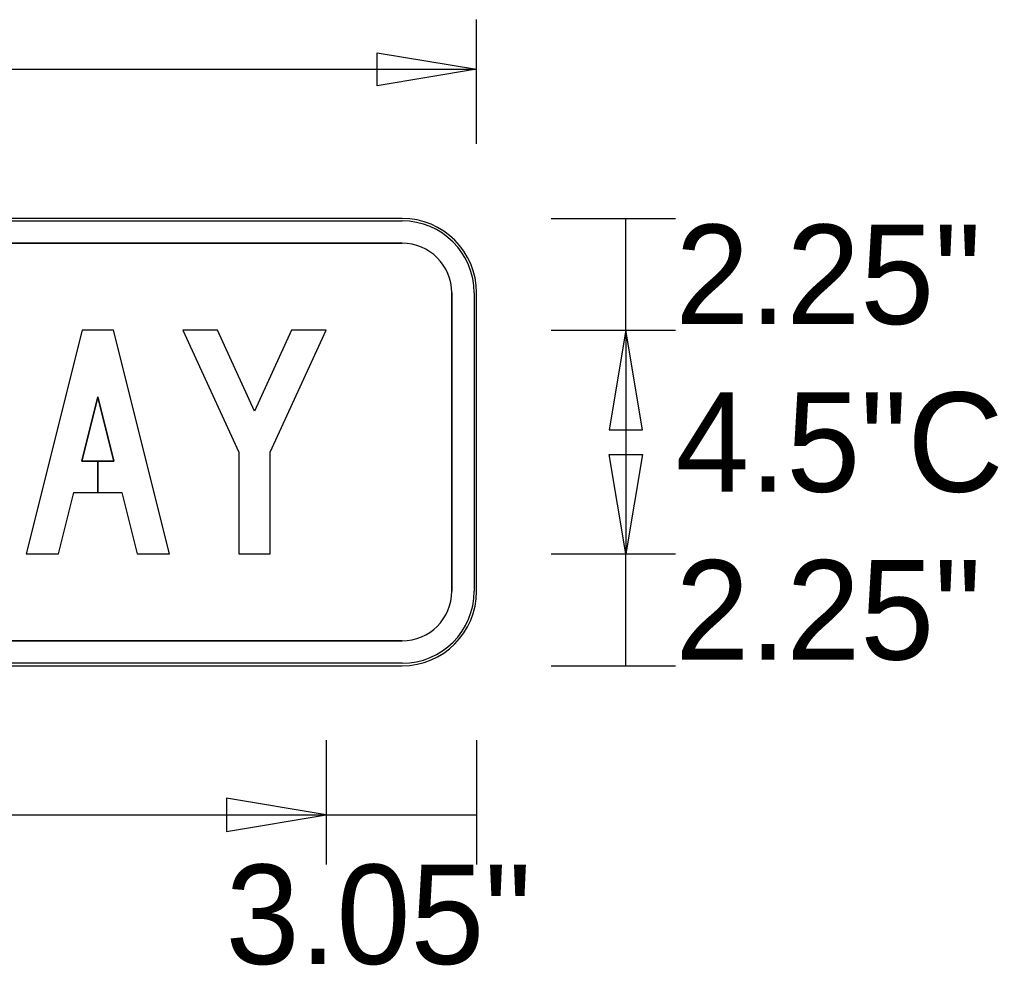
# Model space of a CAD drawing. Extents: x -875 to -645, y -2221 to -2162.
# Drawn here: x -870.243 to -868.602, y -2197.969 to -2196.383 of the extents above; entities that cross this region are included whole.
import ezdxf

# ---------------------------------------------------------------- set-up
doc = ezdxf.new("R2010")
doc.units = 0
for name, color, linetype in [('PlotBorder_dp', 7, 'Continuous'), ('SheetBorder_dp', 7, 'Continuous'), ('SheetLines_dp', 7, 'Continuous'), ('TextMinor', 7, 'Continuous')]:
    doc.layers.add(name, color=color, linetype=linetype)

msp = doc.modelspace()

# ---------------------------------------------------------------- linework, layer by layer
at = {"layer": 'PlotBorder_dp'}
for p, q in [((-869.6014, -2196.7163), (-873.3514, -2196.7163)), ((-873.3514, -2196.758), (-869.6014, -2196.758)), ((-869.5181, -2196.8413), (-869.5181, -2197.3413)), ((-869.4764, -2197.3413), (-869.4764, -2196.8413)), ((-869.6014, -2197.4246), (-873.351, -2197.4246)), ((-873.351, -2197.4663), (-869.6014, -2197.4663))]:
    msp.add_line(p, q, dxfattribs=at)
for points in [[(-870.1114, -2197.1232), (-870.1384, -2197.1232), (-870.1114, -2197.0153), (-870.0844, -2197.1232), (-870.1114, -2197.1232), (-870.1114, -2197.1757), (-870.0713, -2197.1757), (-870.0455, -2197.2788), (-869.9914, -2197.2788), (-870.0851, -2196.9038), (-870.1376, -2196.9038), (-870.2314, -2197.2788), (-870.1773, -2197.2788), (-870.1515, -2197.1757), (-870.1114, -2197.1757)], [(-869.8751, -2197.1082), (-869.8751, -2197.2788), (-869.8226, -2197.2788), (-869.8226, -2197.1082), (-869.7289, -2196.9038), (-869.7867, -2196.9038), (-869.8489, -2197.0395), (-869.9111, -2196.9038), (-869.9689, -2196.9038)]]:
    msp.add_lwpolyline(points, close=True, dxfattribs=at)
for centre, radius, start, end in [((-869.6014, -2196.8413), 0.125, 0, 90), ((-869.6014, -2196.8413), 0.0833, 0, 90), ((-869.6014, -2197.3413), 0.125, 270, 0), ((-869.6014, -2197.3413), 0.0833, 270, 0)]:
    msp.add_arc(centre, radius, start, end, dxfattribs=at)
at = {"layer": 'SheetBorder_dp'}
for p, q in [((-869.6014, -2196.7163), (-873.3514, -2196.7163)), ((-869.6014, -2196.7163), (-873.3514, -2196.7163)), ((-869.6014, -2196.7163), (-873.3514, -2196.7163)), ((-873.3514, -2196.7205), (-869.6014, -2196.7205)), ((-873.3514, -2196.758), (-869.6014, -2196.758)), ((-869.5181, -2196.8413), (-869.5181, -2197.3413)), ((-869.4806, -2196.8413), (-869.4806, -2197.3413)), ((-869.4764, -2197.3413), (-869.4764, -2196.8413)), ((-869.4764, -2197.3413), (-869.4764, -2196.8413)), ((-869.4764, -2197.3413), (-869.4764, -2196.8413)), ((-869.6014, -2197.4246), (-873.351, -2197.4246)), ((-869.6014, -2197.4621), (-873.3514, -2197.4621)), ((-873.3514, -2197.4663), (-869.6014, -2197.4663)), ((-873.3514, -2197.4663), (-869.6014, -2197.4663)), ((-873.351, -2197.4663), (-869.6014, -2197.4663))]:
    msp.add_line(p, q, dxfattribs=at)
for points in [[(-870.1114, -2197.1232), (-870.1384, -2197.1232), (-870.1114, -2197.0153), (-870.0844, -2197.1232), (-870.1114, -2197.1232), (-870.1114, -2197.1757), (-870.0713, -2197.1757), (-870.0455, -2197.2788), (-869.9914, -2197.2788), (-870.0851, -2196.9038), (-870.1376, -2196.9038), (-870.2314, -2197.2788), (-870.1773, -2197.2788), (-870.1515, -2197.1757), (-870.1114, -2197.1757)], [(-869.8751, -2197.1082), (-869.8751, -2197.2788), (-869.8226, -2197.2788), (-869.8226, -2197.1082), (-869.7289, -2196.9038), (-869.7867, -2196.9038), (-869.8489, -2197.0395), (-869.9111, -2196.9038), (-869.9689, -2196.9038)]]:
    msp.add_lwpolyline(points, close=True, dxfattribs=at)
for centre, radius, start, end in [((-869.6014, -2196.8413), 0.125, 0, 90), ((-869.6014, -2196.8413), 0.125, 0, 90), ((-869.6014, -2196.8413), 0.125, 0, 90), ((-869.6014, -2196.8413), 0.1208, 0, 90), ((-869.6014, -2196.8413), 0.0833, 0, 90), ((-869.6014, -2197.3413), 0.125, 270, 0), ((-869.6014, -2197.3413), 0.125, 270, 0), ((-869.6014, -2197.3413), 0.0833, 270, 0), ((-869.6014, -2197.3413), 0.125, 270, 0), ((-869.6014, -2197.3413), 0.1208, 270, 0)]:
    msp.add_arc(centre, radius, start, end, dxfattribs=at)
at = {"layer": 'SheetLines_dp'}
for p, q in [((-869.6014, -2196.7163), (-873.3514, -2196.7163)), ((-869.6014, -2196.758), (-873.3514, -2196.758)), ((-869.5181, -2197.3413), (-869.5181, -2196.8413)), ((-869.4764, -2197.3413), (-869.4764, -2196.8413)), ((-873.3514, -2197.4246), (-869.6014, -2197.4246)), ((-873.3514, -2197.4663), (-869.6014, -2197.4663))]:
    msp.add_line(p, q, dxfattribs=at)
for points in [[(-870.1515, -2197.1757), (-870.0713, -2197.1757), (-870.0455, -2197.2788), (-869.9914, -2197.2788), (-870.0851, -2196.9038), (-870.1376, -2196.9038), (-870.2314, -2197.2788), (-870.1773, -2197.2788)], [(-869.8751, -2197.1082), (-869.8751, -2197.2788), (-869.8226, -2197.2788), (-869.8226, -2197.1082), (-869.7289, -2196.9038), (-869.7867, -2196.9038), (-869.8489, -2197.0395), (-869.9111, -2196.9038), (-869.9689, -2196.9038)], [(-870.0844, -2197.1232), (-870.1114, -2197.0153), (-870.1384, -2197.1232)]]:
    msp.add_lwpolyline(points, close=True, dxfattribs=at)
for centre, radius, start, end in [((-869.6014, -2196.8413), 0.125, 0, 90), ((-869.6014, -2196.8413), 0.0833, 0, 90), ((-869.6014, -2197.3413), 0.125, 270, 0), ((-869.6014, -2197.3413), 0.0833, 270, 0)]:
    msp.add_arc(centre, radius, start, end, dxfattribs=at)
at = {"layer": 'TextMinor'}
for p, q in [((-869.4764, -2196.5913), (-869.4764, -2196.383)), ((-873.4764, -2196.4663), (-869.4764, -2196.4663)), ((-869.3514, -2196.7163), (-869.1431, -2196.7163)), ((-869.2264, -2196.9038), (-869.2264, -2196.7163)), ((-869.3514, -2196.9038), (-869.1431, -2196.9038)), ((-869.3514, -2196.9038), (-869.1431, -2196.9038)), ((-869.2264, -2196.9038), (-869.2264, -2197.2788)), ((-869.3514, -2197.2788), (-869.1431, -2197.2788)), ((-869.3514, -2197.2788), (-869.1431, -2197.2788)), ((-869.2264, -2197.4663), (-869.2264, -2197.2788)), ((-869.3514, -2197.4663), (-869.1431, -2197.4663)), ((-869.7289, -2197.5913), (-869.7289, -2197.7996)), ((-869.7289, -2197.5913), (-869.7289, -2197.7996)), ((-869.4764, -2197.5913), (-869.4764, -2197.7996)), ((-873.2239, -2197.7163), (-869.7289, -2197.7163)), ((-869.7289, -2197.7163), (-869.4764, -2197.7163))]:
    msp.add_line(p, q, dxfattribs=at)
for points in [[(-869.4764, -2196.4663), (-869.6431, -2196.4941), (-869.6431, -2196.4385)], [(-869.2264, -2196.9038), (-869.2542, -2197.0705), (-869.1986, -2197.0705)], [(-869.2264, -2197.2788), (-869.2542, -2197.1121), (-869.1986, -2197.1121)], [(-869.7289, -2197.7163), (-869.8956, -2197.6885), (-869.8956, -2197.7441)]]:
    msp.add_lwpolyline(points, close=True, dxfattribs=at)

# ---------------------------------------------------------------- texts
for s, p in [('2.25"', (-869.1431, -2196.8934)), ('4.5"C', (-869.1431, -2197.1746)), ('2.25"', (-869.1431, -2197.4559)), ('3.05"', (-869.8972, -2197.9663))]:
    msp.add_text(s, height=0.16667, dxfattribs=at).set_placement(p)

doc.saveas('drawing.dxf')
